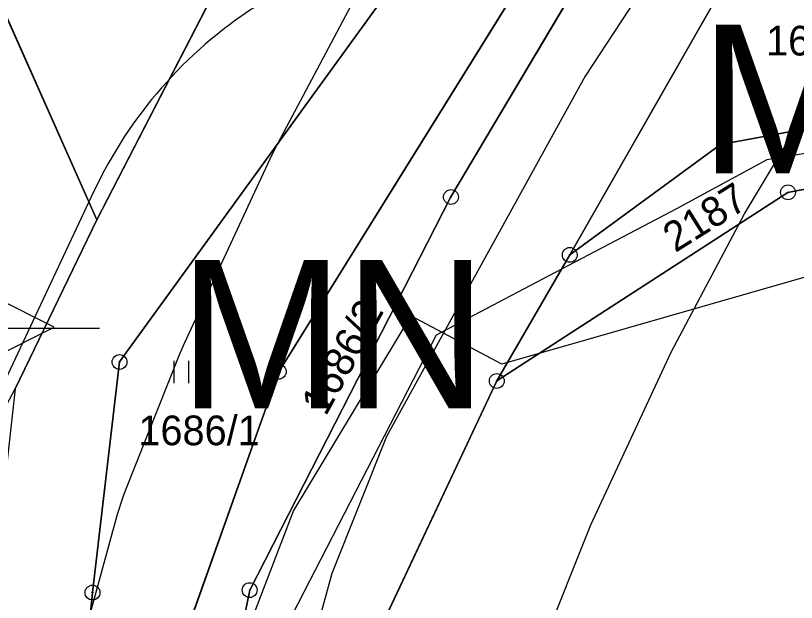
# Model space of a CAD drawing. Extents: x -706130 to -698555, y -971544 to -967260.
# Drawn here: x -704462.3 to -704409.7, y -970498.9 to -970459.4 of the extents above; entities that cross this region are included whole.
import ezdxf

# ---------------------------------------------------------------- set-up
doc = ezdxf.new("R2010")
doc.units = 0
for name, color, linetype in [('Architektonicky cenná stavba drobna krizky S', 7, 'Continuous'), ('BPEJ hranice S', 7, 'Continuous'), ('BPEJ I-II trida ochrany S', 7, 'Continuous'), ('Docházková izochrona - VLAK N', 7, 'Continuous'), ('Implicitní', 7, 'Continuous'), ('KN_Hranice_parcel', 7, 'Continuous'), ('KN_Parcelni cisla', 7, 'Continuous'), ('KN_Polygon parcely', 7, 'Continuous'), ('KN_POZEMKY_10_LESNI POZEMEK', 7, 'Continuous'), ('KN_POZEMKY_14_OSTATNI PLOCHA', 7, 'Continuous'), ('KN_POZEMKY_2_ORNA PUDA', 7, 'Continuous'), ('KN_POZEMKY_7_TTP', 7, 'Continuous'), ('KN_VYUZITI_16_ostatni plocha_silnice', 7, 'Continuous'), ('KN_VYUZITI_17_ostatni plocha_ostatni komunikace', 7, 'Continuous'), ('KN_VYUZITI_26_ostatni plocha_jina plocha', 7, 'Continuous'), ('KN_Značky bodu BP', 7, 'Continuous'), ('KN_Značky kultur', 7, 'Continuous'), ('Komunikace III třídy osy S', 7, 'Continuous'), ('OP lesa 30 m', 7, 'Continuous'), ('OP silnic S', 7, 'Continuous'), ('Plochy doprava silniční - silnice III třídy S', 7, 'Continuous'), ('Plochy lesní všeobecné S', 7, 'Continuous'), ('Plochy smíšené nezastavěného území všeobecné S', 7, 'Continuous'), ('Plochy verejnych prostranstvi - komunikace ostatni S', 7, 'Continuous'), ('Plochy zemědělské všeobecné CELEK S', 7, 'Continuous'), ('Regulační bloky v krajině S', 7, 'Continuous'), ('Regulační bloky zastavěné S', 7, 'Continuous'), ('Regulační kódy v krajině S', 7, 'Continuous'), ('Trasy cykloturistické N', 7, 'Continuous'), ('VÝŠKOPIS_vrstevnice hlavní', 7, 'Continuous')]:
    doc.layers.add(name, color=color, linetype=linetype)

# ---------------------------------------------------------------- blocks, each defined once
blk = doc.blocks.new('UNNAMED')
at = {"layer": 'Implicitní'}
for p, q in [((0, -0.5), (0, 0.5)), ((-0.5, 0), (0.5, 0))]:
    blk.add_line(p, q, dxfattribs=at)

msp = doc.modelspace()

# ---------------------------------------------------------------- linework, layer by layer
at = {"layer": 'Architektonicky cenná stavba drobna krizky S'}
msp.add_lwpolyline([(-704465.704, -970474.368), (-704467.704, -970478.368), (-704471.704, -970480.368), (-704467.704, -970482.368), (-704465.704, -970486.368), (-704463.704, -970482.368), (-704459.704, -970480.368), (-704463.704, -970478.368)], close=True, dxfattribs=at)
at = {"layer": 'BPEJ hranice S'}
msp.add_lwpolyline([(-704380.05, -970468.36), (-704382.69, -970470.66), (-704383.398, -970469.9), (-704385.263, -970471.608), (-704389.567, -970467.322), (-704389.761, -970467.129), (-704391.176, -970465.721), (-704411.691, -970469.098), (-704417.768, -970472.39), (-704425.521, -970476.466), (-704433.955, -970480.902), (-704443.656, -970499.75)], dxfattribs=at)
at = {"layer": 'BPEJ I-II trida ochrany S'}
for p, q in [((-704410.11, -970449.5), (-704424.96, -970475.5)), ((-704456.83, -970473.13), (-704445.53, -970451.26)), ((-704444.57, -970483.37), (-704428.64, -970457.77)), ((-704437.52, -970458.16), (-704455.3, -970482.71)), ((-704414.8, -970468.06), (-704390.72, -970463.62)), ((-704424.96, -970475.5), (-704414.8, -970468.06)), ((-704462.33, -970484.51), (-704456.83, -970473.13)), ((-704455.3, -970482.71), (-704457.12, -970498.24)), ((-704450.6, -970500.34), (-704444.57, -970483.37)), ((-704457.12, -970498.24), (-704460.86, -970536.48))]:
    msp.add_line(p, q, dxfattribs=at)
at = {"layer": 'Docházková izochrona - VLAK N'}
msp.add_circle((-704165.451, -969778.767), 800, dxfattribs=at)
at = {"layer": 'KN_Hranice_parcel'}
for p, q in [((-704456.83, -970473.13), (-704445.53, -970451.26)), ((-704462.33, -970484.51), (-704456.83, -970473.13)), ((-704424.96, -970475.5), (-704429.88, -970483.99))]:
    msp.add_line(p, q, dxfattribs=at)
for points in [[(-704456.83, -970473.13), (-704474.11, -970434.34), (-704492.75, -970364), (-704485.71, -970343.76), (-704482.97, -970327.34), (-704535.5, -970303.67), (-704598.61, -970265.93), (-704627.27, -970138.62)], [(-704398.62, -970429.46), (-704399.6, -970431.05), (-704410.11, -970449.5), (-704424.96, -970475.5)], [(-704449.76, -970553.12), (-704452.04, -970539.51), (-704449.79, -970513.98), (-704446.53, -970498.08), (-704432.97, -970471.6), (-704420.1, -970449.92), (-704410.54, -970434.28)], [(-704417.08, -970440.07), (-704437.52, -970458.16), (-704455.3, -970482.71), (-704457.12, -970498.24), (-704460.86, -970536.48), (-704460.37, -970544.21)], [(-704457.5, -970545.33), (-704457.1, -970528.92), (-704450.6, -970500.34), (-704444.57, -970483.37), (-704428.64, -970457.77), (-704417.93, -970441.37)], [(-704424.96, -970475.5), (-704414.8, -970468.06), (-704390.72, -970463.62)], [(-704386.37, -970466.71), (-704410.26, -970471.29), (-704429.88, -970483.99)], [(-704429.88, -970483.99), (-704437.86, -970500.93), (-704440.81, -970512.35), (-704444.18, -970537.3), (-704437.59, -970564.83), (-704389.48, -970641.61), (-704384.25, -970653.17), (-704379.8, -970666.04), (-704377.6, -970678.33), (-704377.41, -970702.19), (-704385.12, -970737.85), (-704395, -970781.85), (-704396.32, -970808.97), (-704393.81, -970830.29), (-704393.06, -970832.89)]]:
    msp.add_lwpolyline(points, dxfattribs=at)
at = {"layer": 'KN_Polygon parcely'}
for points in [[(-704692.15, -970629.07), (-704615.18, -970606.86), (-704623.63, -970586.56), (-704629.62, -970547.2), (-704625.02, -970520.05), (-704610.43, -970513.53), (-704587.04, -970506.57), (-704554.75, -970507.86), (-704523.94, -970513.88), (-704487.95, -970521.55), (-704481.76, -970519.89), (-704475.26, -970516.19), (-704471.7, -970502.08), (-704462.33, -970484.51), (-704456.83, -970473.13), (-704474.11, -970434.34), (-704492.75, -970364)], [(-704492.75, -970364), (-704474.11, -970434.34), (-704456.83, -970473.13), (-704445.53, -970451.26), (-704452.01, -970442.24), (-704460.72, -970426.66), (-704421.1, -970404.49)], [(-704392.51, -970404.97), (-704410.54, -970434.28), (-704420.1, -970449.92), (-704432.97, -970471.6), (-704446.53, -970498.08), (-704449.79, -970513.98), (-704452.04, -970539.51), (-704449.76, -970553.12), (-704449.12, -970558.06), (-704448.09, -970560.09), (-704440.4, -970575.2), (-704397.96, -970643.06), (-704390, -970659.17), (-704385.4, -970680.33), (-704389.28, -970704.44), (-704391.73, -970719.71)], [(-704391.73, -970719.71), (-704389.28, -970704.44), (-704388.64, -970691.38), (-704415.64, -970625.27), (-704435.23, -970594.85), (-704456.48, -970566.41), (-704456.72, -970565.07), (-704459.46, -970549.4), (-704460.37, -970544.21), (-704460.86, -970536.48), (-704457.12, -970498.24), (-704455.3, -970482.71), (-704437.52, -970458.16), (-704417.08, -970440.07), (-704416.33, -970439.4), (-704409.13, -970429.05), (-704396.57, -970408.3)], [(-704385.12, -970737.85), (-704377.41, -970702.19), (-704377.6, -970678.33), (-704379.8, -970666.04), (-704384.25, -970653.17), (-704389.48, -970641.61), (-704437.59, -970564.83), (-704444.18, -970537.3), (-704440.81, -970512.35), (-704437.86, -970500.93), (-704429.88, -970483.99), (-704424.96, -970475.5), (-704410.11, -970449.5), (-704399.6, -970431.05), (-704398.62, -970429.46), (-704397.28, -970427.29), (-704394.69, -970423.1), (-704386.46, -970409.76)], [(-704403.45, -970413.95), (-704417.91, -970426.34), (-704444.32, -970449.04), (-704445.53, -970451.26), (-704456.83, -970473.13), (-704462.33, -970484.51), (-704467.66, -970532.1), (-704464.83, -970542.91), (-704459.85, -970569.07), (-704438.13, -970597.66), (-704419.24, -970627.4), (-704392.84, -970693.06), (-704394.53, -970717.38)], [(-704338.27, -970419.08), (-704351.28, -970442.67), (-704352.57, -970444.4), (-704352.11, -970446.17), (-704347.68, -970463.22), (-704349.74, -970487.8), (-704373.16, -970465.99), (-704375.18, -970464.11), (-704380.05, -970468.36), (-704382.69, -970470.66), (-704386.37, -970466.71), (-704410.26, -970471.29), (-704429.88, -970483.99), (-704437.86, -970500.93), (-704440.81, -970512.35), (-704444.18, -970537.3), (-704437.59, -970564.83), (-704389.48, -970641.61), (-704384.25, -970653.17), (-704379.8, -970666.04), (-704377.6, -970678.33), (-704377.41, -970702.19), (-704385.12, -970737.85)]]:
    msp.add_lwpolyline(points, dxfattribs=at)
for points in [[(-704414.8, -970468.06), (-704390.72, -970463.62), (-704401.99, -970449.95), (-704390.95, -970438.63), (-704389.94, -970437.52), (-704398.62, -970429.46), (-704399.6, -970431.05), (-704410.11, -970449.5), (-704424.96, -970475.5)], [(-704432.97, -970471.6), (-704420.1, -970449.92), (-704410.54, -970434.28), (-704416.33, -970439.4), (-704417.08, -970440.07), (-704417.93, -970441.37), (-704428.64, -970457.77), (-704444.57, -970483.37), (-704450.6, -970500.34), (-704457.1, -970528.92), (-704457.5, -970545.33), (-704457.53, -970546.6), (-704449.76, -970553.12), (-704452.04, -970539.51), (-704449.79, -970513.98), (-704446.53, -970498.08)], [(-704460.37, -970544.21), (-704457.53, -970546.6), (-704457.5, -970545.33), (-704457.1, -970528.92), (-704450.6, -970500.34), (-704444.57, -970483.37), (-704428.64, -970457.77), (-704417.93, -970441.37), (-704417.08, -970440.07), (-704437.52, -970458.16), (-704455.3, -970482.71), (-704457.12, -970498.24), (-704460.86, -970536.48)], [(-704429.88, -970483.99), (-704410.26, -970471.29), (-704386.37, -970466.71), (-704387.29, -970465.73), (-704388.89, -970465.85), (-704390.72, -970463.62), (-704414.8, -970468.06), (-704424.96, -970475.5)]]:
    msp.add_lwpolyline(points, close=True, dxfattribs=at)
at = {"layer": 'KN_POZEMKY_10_LESNI POZEMEK'}
for p, q in [((-704410.26, -970471.29), (-704386.37, -970466.71)), ((-704429.88, -970483.99), (-704410.26, -970471.29)), ((-704437.86, -970500.93), (-704429.88, -970483.99))]:
    msp.add_line(p, q, dxfattribs=at)
at = {"layer": 'KN_POZEMKY_14_OSTATNI PLOCHA'}
for p, q in [((-704410.11, -970449.5), (-704424.96, -970475.5)), ((-704432.97, -970471.6), (-704420.1, -970449.92)), ((-704420.1, -970449.92), (-704432.97, -970471.6)), ((-704456.83, -970473.13), (-704445.53, -970451.26)), ((-704444.57, -970483.37), (-704428.64, -970457.77)), ((-704437.52, -970458.16), (-704455.3, -970482.71)), ((-704414.8, -970468.06), (-704390.72, -970463.62)), ((-704386.37, -970466.71), (-704410.26, -970471.29)), ((-704424.96, -970475.5), (-704414.8, -970468.06)), ((-704446.53, -970498.08), (-704432.97, -970471.6)), ((-704432.97, -970471.6), (-704446.53, -970498.08)), ((-704410.26, -970471.29), (-704429.88, -970483.99)), ((-704462.33, -970484.51), (-704456.83, -970473.13)), ((-704424.96, -970475.5), (-704429.88, -970483.99)), ((-704429.88, -970483.99), (-704424.96, -970475.5)), ((-704455.3, -970482.71), (-704457.12, -970498.24)), ((-704450.6, -970500.34), (-704444.57, -970483.37)), ((-704429.88, -970483.99), (-704437.86, -970500.93)), ((-704457.12, -970498.24), (-704460.86, -970536.48)), ((-704449.79, -970513.98), (-704446.53, -970498.08)), ((-704446.53, -970498.08), (-704449.79, -970513.98))]:
    msp.add_line(p, q, dxfattribs=at)
at = {"layer": 'KN_POZEMKY_2_ORNA PUDA'}
for p, q in [((-704474.11, -970434.34), (-704456.83, -970473.13)), ((-704456.83, -970473.13), (-704462.33, -970484.51))]:
    msp.add_line(p, q, dxfattribs=at)
at = {"layer": 'KN_POZEMKY_7_TTP'}
for p, q in [((-704456.83, -970473.13), (-704474.11, -970434.34)), ((-704424.96, -970475.5), (-704410.11, -970449.5)), ((-704445.53, -970451.26), (-704456.83, -970473.13)), ((-704428.64, -970457.77), (-704444.57, -970483.37)), ((-704455.3, -970482.71), (-704437.52, -970458.16)), ((-704390.72, -970463.62), (-704414.8, -970468.06)), ((-704414.8, -970468.06), (-704424.96, -970475.5)), ((-704457.12, -970498.24), (-704455.3, -970482.71)), ((-704444.57, -970483.37), (-704450.6, -970500.34)), ((-704460.86, -970536.48), (-704457.12, -970498.24))]:
    msp.add_line(p, q, dxfattribs=at)
at = {"layer": 'KN_VYUZITI_16_ostatni plocha_silnice'}
for p, q in [((-704410.11, -970449.5), (-704424.96, -970475.5)), ((-704432.97, -970471.6), (-704420.1, -970449.92)), ((-704446.53, -970498.08), (-704432.97, -970471.6)), ((-704424.96, -970475.5), (-704429.88, -970483.99)), ((-704429.88, -970483.99), (-704437.86, -970500.93)), ((-704449.79, -970513.98), (-704446.53, -970498.08))]:
    msp.add_line(p, q, dxfattribs=at)
at = {"layer": 'KN_VYUZITI_17_ostatni plocha_ostatni komunikace'}
for p, q in [((-704456.83, -970473.13), (-704445.53, -970451.26)), ((-704437.52, -970458.16), (-704455.3, -970482.71)), ((-704414.8, -970468.06), (-704390.72, -970463.62)), ((-704386.37, -970466.71), (-704410.26, -970471.29)), ((-704424.96, -970475.5), (-704414.8, -970468.06)), ((-704410.26, -970471.29), (-704429.88, -970483.99)), ((-704462.33, -970484.51), (-704456.83, -970473.13)), ((-704429.88, -970483.99), (-704424.96, -970475.5)), ((-704455.3, -970482.71), (-704457.12, -970498.24)), ((-704457.12, -970498.24), (-704460.86, -970536.48))]:
    msp.add_line(p, q, dxfattribs=at)
at = {"layer": 'KN_VYUZITI_26_ostatni plocha_jina plocha'}
for p, q in [((-704420.1, -970449.92), (-704432.97, -970471.6)), ((-704444.57, -970483.37), (-704428.64, -970457.77)), ((-704432.97, -970471.6), (-704446.53, -970498.08)), ((-704450.6, -970500.34), (-704444.57, -970483.37)), ((-704446.53, -970498.08), (-704449.79, -970513.98))]:
    msp.add_line(p, q, dxfattribs=at)
at = {"layer": 'KN_Značky bodu BP'}
for centre, radius in [((-704432.97, -970471.6), 0.5), ((-704410.26, -970471.29), 0.5), ((-704432.97, -970471.6), 0.0303), ((-704410.26, -970471.29), 0.0303), ((-704424.96, -970475.5), 0.5), ((-704424.96, -970475.5), 0.0303), ((-704455.3, -970482.71), 0.5), ((-704455.3, -970482.71), 0.0303), ((-704444.57, -970483.37), 0.5), ((-704444.57, -970483.37), 0.0303), ((-704429.88, -970483.99), 0.5), ((-704429.88, -970483.99), 0.0303), ((-704457.12, -970498.24), 0.5), ((-704446.53, -970498.08), 0.5), ((-704457.12, -970498.24), 0.0303), ((-704446.53, -970498.08), 0.0303)]:
    msp.add_circle(centre, radius, dxfattribs=at)
at = {"layer": 'KN_Značky kultur'}
for p, q in [((-704451.621, -970484.14), (-704451.621, -970482.64)), ((-704450.62, -970484.14), (-704450.62, -970482.64))]:
    msp.add_line(p, q, dxfattribs=at)
at = {"layer": 'Komunikace III třídy osy S'}
msp.add_lwpolyline([(-704392.36, -970410.73), (-704399.98, -970422.96), (-704416.579, -970452.251), (-704423.936, -970463.473), (-704430.079, -970474.624), (-704437.32, -970487.74), (-704440.99, -970496.95), (-704443.639, -970506.619), (-704445.45, -970514.71), (-704446.24, -970521.03), (-704446.95, -970529.22), (-704447.27, -970537.94), (-704447.22, -970543.68), (-704446.69, -970550.7), (-704445.73, -970555.16), (-704444.85, -970557.5), (-704443.66, -970559.94), (-704441.03, -970564.8), (-704437.56, -970570.95), (-704394.186, -970641.224)], dxfattribs=at)
at = {"layer": 'OP lesa 30 m'}
msp.add_line((-704457.019, -970471.205), (-704464.999, -970488.145), dxfattribs=at)
msp.add_arc((-704429.88, -970483.99), 30, 122.9149, 154.7761, dxfattribs=at)
at = {"layer": 'OP silnic S'}
for points in [[(-704412.691, -970414.996), (-704430.611, -970443.433), (-704430.79, -970443.725), (-704439.19, -970457.757), (-704439.514, -970458.336), (-704444.824, -970468.356), (-704445.17, -970469.053), (-704450.92, -970481.413), (-704451.254, -970482.187), (-704454.924, -970491.397), (-704455.085, -970491.82), (-704455.457, -970492.987), (-704458.106, -970502.656)], [(-704379.52, -970633.151), (-704424.717, -970563.188), (-704427.901, -970557.544), (-704430.317, -970553.08), (-704431.058, -970551.559), (-704431.299, -970550.919), (-704431.81, -970548.547), (-704432.225, -970543.049), (-704432.268, -970538.15), (-704431.974, -970530.143), (-704431.32, -970522.609), (-704430.655, -970517.284), (-704429.078, -970510.241), (-704426.745, -970501.723), (-704423.542, -970493.685), (-704418.134, -970482.06), (-704413.189, -970472.73), (-704405.138, -970459.282), (-704399.94, -970451.033), (-704400.323, -970450.591), (-704398.657, -970448.996), (-704387.269, -970430.925), (-704379.656, -970418.705)]]:
    msp.add_lwpolyline(points, dxfattribs=at)
at = {"layer": 'Plochy doprava silniční - silnice III třídy S'}
for p, q in [((-704424.96, -970475.5), (-704410.11, -970449.5)), ((-704420.1, -970449.92), (-704432.97, -970471.6)), ((-704432.97, -970471.6), (-704446.53, -970498.08)), ((-704429.88, -970483.99), (-704424.96, -970475.5)), ((-704437.86, -970500.93), (-704429.88, -970483.99)), ((-704446.53, -970498.08), (-704449.79, -970513.98))]:
    msp.add_line(p, q, dxfattribs=at)
at = {"layer": 'Plochy lesní všeobecné S'}
for p, q in [((-704386.37, -970466.71), (-704410.26, -970471.29)), ((-704410.26, -970471.29), (-704429.88, -970483.99)), ((-704429.88, -970483.99), (-704437.86, -970500.93))]:
    msp.add_line(p, q, dxfattribs=at)
at = {"layer": 'Plochy smíšené nezastavěného území všeobecné S'}
for p, q in [((-704474.11, -970434.34), (-704456.83, -970473.13)), ((-704410.11, -970449.5), (-704424.96, -970475.5)), ((-704432.97, -970471.6), (-704420.1, -970449.92)), ((-704456.83, -970473.13), (-704445.53, -970451.26)), ((-704446.53, -970498.08), (-704432.97, -970471.6)), ((-704424.96, -970475.5), (-704429.88, -970483.99)), ((-704455.3, -970482.71), (-704457.12, -970498.24)), ((-704457.12, -970498.24), (-704460.86, -970536.48)), ((-704449.79, -970513.98), (-704446.53, -970498.08))]:
    msp.add_line(p, q, dxfattribs=at)
for points in [[(-704417.08, -970440.07), (-704437.52, -970458.16), (-704455.3, -970482.71)], [(-704429.88, -970483.99), (-704410.26, -970471.29), (-704386.37, -970466.71)]]:
    msp.add_lwpolyline(points, dxfattribs=at)
at = {"layer": 'Plochy verejnych prostranstvi - komunikace ostatni S'}
for p, q in [((-704445.53, -970451.26), (-704456.83, -970473.13)), ((-704456.83, -970473.13), (-704462.33, -970484.51))]:
    msp.add_line(p, q, dxfattribs=at)
msp.add_lwpolyline([(-704460.37, -970544.21), (-704460.86, -970536.48), (-704457.12, -970498.24), (-704455.3, -970482.71), (-704437.52, -970458.16), (-704417.08, -970440.07)], dxfattribs=at)
at = {"layer": 'Plochy zemědělské všeobecné CELEK S'}
for p, q in [((-704456.83, -970473.13), (-704474.11, -970434.34)), ((-704462.33, -970484.51), (-704456.83, -970473.13))]:
    msp.add_line(p, q, dxfattribs=at)
at = {"layer": 'Regulační bloky v krajině S'}
for p, q in [((-704474.11, -970434.34), (-704456.83, -970473.13)), ((-704456.83, -970473.13), (-704474.11, -970434.34)), ((-704410.11, -970449.5), (-704424.96, -970475.5)), ((-704432.97, -970471.6), (-704420.1, -970449.92)), ((-704456.83, -970473.13), (-704445.53, -970451.26)), ((-704386.37, -970466.71), (-704410.26, -970471.29)), ((-704446.53, -970498.08), (-704432.97, -970471.6)), ((-704410.26, -970471.29), (-704429.88, -970483.99)), ((-704462.33, -970484.51), (-704456.83, -970473.13)), ((-704424.96, -970475.5), (-704429.88, -970483.99)), ((-704455.3, -970482.71), (-704457.12, -970498.24)), ((-704429.88, -970483.99), (-704437.86, -970500.93)), ((-704457.12, -970498.24), (-704460.86, -970536.48)), ((-704449.79, -970513.98), (-704446.53, -970498.08))]:
    msp.add_line(p, q, dxfattribs=at)
for points in [[(-704417.08, -970440.07), (-704437.52, -970458.16), (-704455.3, -970482.71)], [(-704429.88, -970483.99), (-704410.26, -970471.29), (-704386.37, -970466.71)]]:
    msp.add_lwpolyline(points, dxfattribs=at)
at = {"layer": 'Regulační bloky zastavěné S'}
for p, q in [((-704424.96, -970475.5), (-704410.11, -970449.5)), ((-704420.1, -970449.92), (-704432.97, -970471.6)), ((-704445.53, -970451.26), (-704456.83, -970473.13)), ((-704432.97, -970471.6), (-704446.53, -970498.08)), ((-704456.83, -970473.13), (-704462.33, -970484.51)), ((-704429.88, -970483.99), (-704424.96, -970475.5)), ((-704437.86, -970500.93), (-704429.88, -970483.99)), ((-704446.53, -970498.08), (-704449.79, -970513.98))]:
    msp.add_line(p, q, dxfattribs=at)
msp.add_lwpolyline([(-704460.37, -970544.21), (-704460.86, -970536.48), (-704457.12, -970498.24), (-704455.3, -970482.71), (-704437.52, -970458.16), (-704417.08, -970440.07)], dxfattribs=at)
at = {"layer": 'Trasy cykloturistické N'}
msp.add_lwpolyline([(-704385.12, -970737.85), (-704377.41, -970702.19), (-704377.6, -970678.33), (-704379.8, -970666.04), (-704389.48, -970641.61), (-704437.59, -970564.83), (-704444.18, -970537.3), (-704440.81, -970512.35), (-704437.86, -970500.93), (-704429.88, -970483.99), (-704424.96, -970475.5), (-704410.11, -970449.5), (-704410.11, -970449.5), (-704398.62, -970429.46), (-704397.28, -970427.29), (-704386.46, -970409.76)], dxfattribs=at)
at = {"layer": 'VÝŠKOPIS_vrstevnice hlavní'}
for points in [[(-704342.203, -970450.847), (-704396.042, -970473.256), (-704429.53, -970482.868), (-704435.679, -970479.596)], [(-704435.679, -970479.596), (-704443.586, -970492.71), (-704447.855, -970503.817), (-704450.203, -970519.836), (-704449.135, -970534.36), (-704449.419, -970544.877), (-704450.275, -970551.298), (-704451.701, -970555.863), (-704453.984, -970558.431), (-704455.411, -970559.002), (-704458.264, -970558.431), (-704459.808, -970557.427), (-704463.436, -970551.019), (-704469.84, -970541.408)]]:
    msp.add_lwpolyline(points, dxfattribs=at)

# ---------------------------------------------------------------- block references
at = {"layer": 'Architektonicky cenná stavba drobna krizky S', "xscale": 18.11164, "yscale": 18.11164}
msp.add_blockref('UNNAMED', (-704465.708, -970480.441), dxfattribs=at)

# ---------------------------------------------------------------- texts
at = {"layer": 'KN_Parcelni cisla'}
for s, p in [('1684/2', (-704411.74, -970462.07)), ('1686/1', (-704454.03, -970488.32))]:
    msp.add_text(s, height=2, dxfattribs=at).set_placement(p)
for s, rotation, p in [('2187', 32, (-704417.859, -970475.38)), ('1686/2', 61, (-704441.406, -970486.422))]:
    msp.add_text(s, height=2, rotation=rotation, dxfattribs=at).set_placement(p)
at = {"layer": 'Regulační kódy v krajině S'}
for p in [(-704416.2, -970470), (-704451.313, -970485.84)]:
    msp.add_text('MN', height=10, dxfattribs=at).set_placement(p)

doc.saveas('drawing.dxf')
